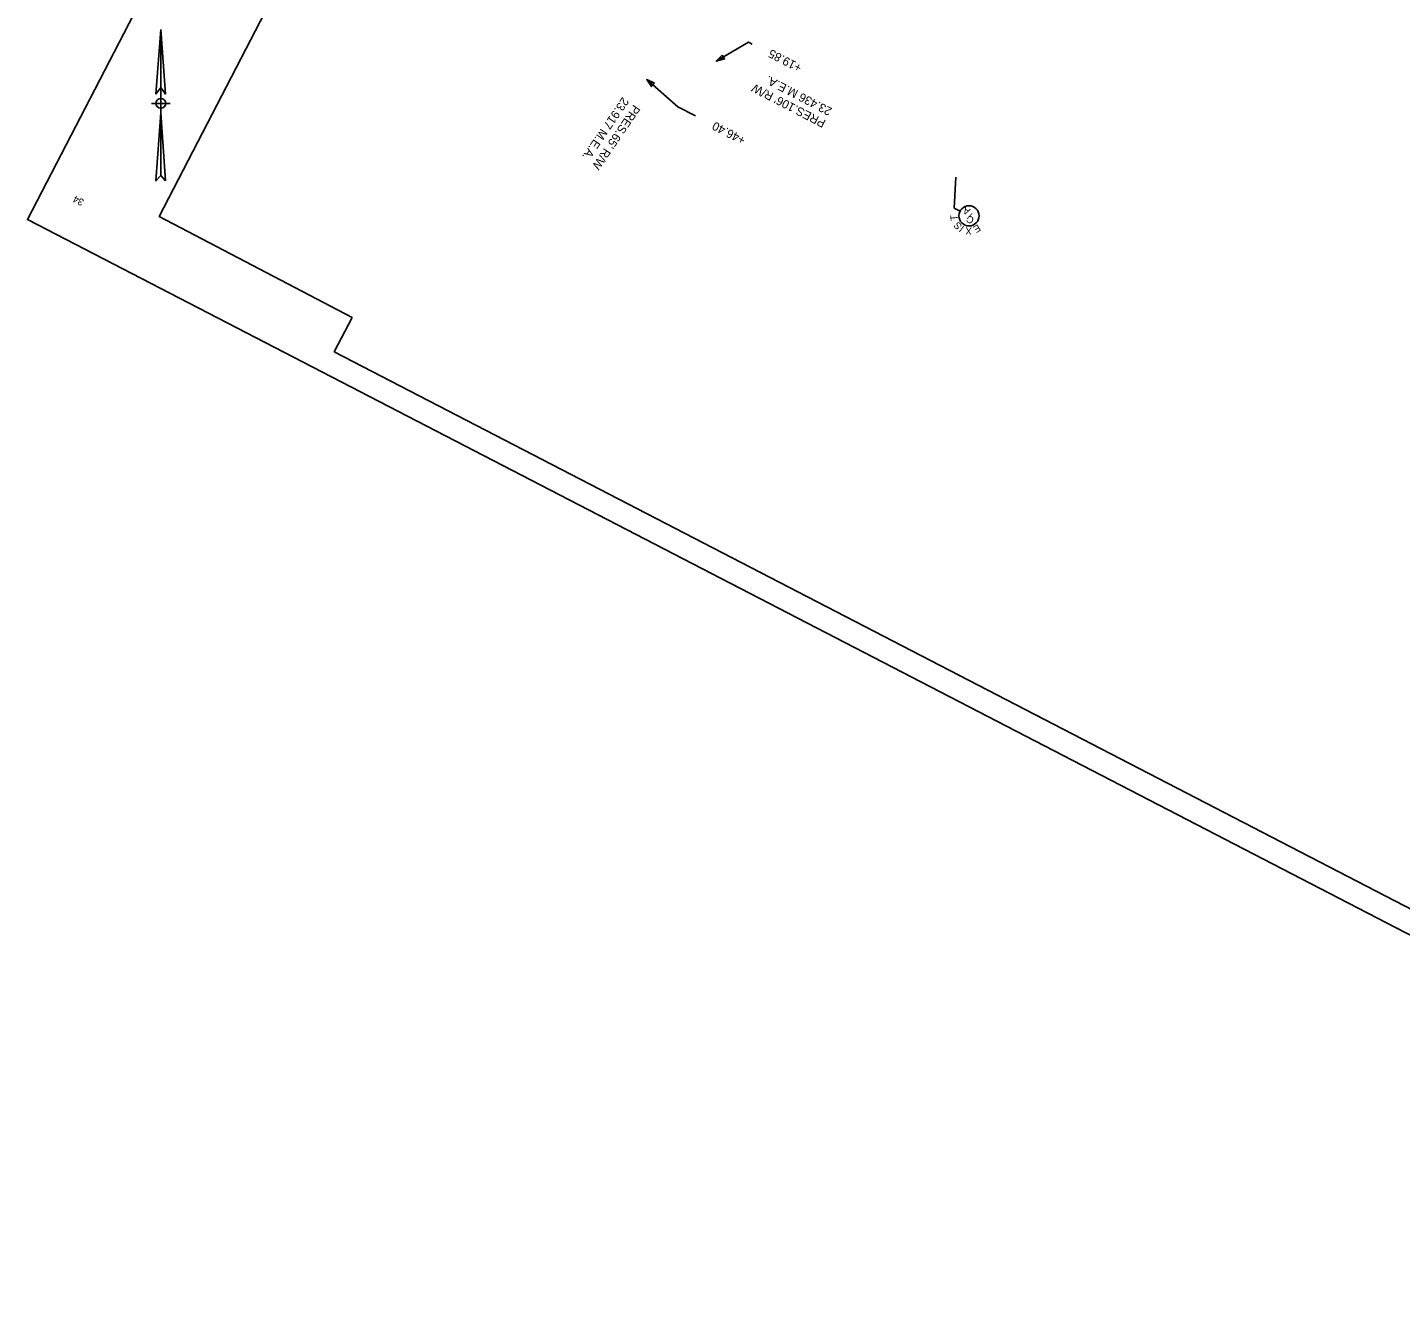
# Model space of a CAD drawing. Extents: x 1605035 to 1606962, y 1094993 to 1096933.
# Drawn here: x 1605035 to 1605999, y 1095130 to 1096034 of the extents above; entities that cross this region are included whole.
import ezdxf

# ---------------------------------------------------------------- set-up
doc = ezdxf.new("R2010")
doc.units = 0
for name, color, linetype in [('RD_EX_Bldg', 7, 'Continuous'), ('RD_EX_DV_Prop', 7, 'Continuous'), ('RD_EX_GuardRail', 7, 'Continuous'), ('RD_EX_H2O', 7, 'Continuous'), ('RD_EX_RW', 7, 'Continuous'), ('RD_HC_Data_Rel', 7, 'Continuous')]:
    doc.layers.add(name, color=color, linetype=linetype)

msp = doc.modelspace()

# ---------------------------------------------------------------- linework, layer by layer
at = {"layer": 'RD_EX_Bldg'}
msp.add_lwpolyline([(1606446.59, 1095187.39), (1605250.25, 1095806.81), (1605262.71, 1095830.87), (1605127.37, 1095901.84), (1605543.16, 1096704.91), (1606875.21, 1096015.23)], close=True, dxfattribs=at)
msp.add_lwpolyline([(1606446.59, 1095187.39), (1605250.25, 1095806.81), (1605262.71, 1095830.87), (1605127.37, 1095901.84), (1605543.16, 1096704.91), (1606875.21, 1096015.23)], close=True, dxfattribs=at)
at = {"layer": 'RD_EX_DV_Prop'}
for p, q in [((1605128.49, 1096033.09), (1605125.07, 1095987.78)), ((1605128.49, 1095992.43), (1605125.07, 1095987.78)), ((1605128.49, 1095992.43), (1605128.49, 1095974.59)), ((1605135.01, 1095981.2), (1605122.03, 1095981.2)), ((1605128.49, 1095974.59), (1605131.9, 1095926.75)), ((1605131.9, 1095926.75), (1605128.49, 1095930.57))]:
    msp.add_line(p, q, dxfattribs=at)
for points in [[(1605128.49, 1096033.09), (1605131.9, 1095987.78), (1605128.49, 1095992.43)], [(1605128.49, 1095974.59), (1605128.49, 1095930.57), (1605125.07, 1095926.75)]]:
    msp.add_lwpolyline(points, close=True, dxfattribs=at)
msp.add_circle((1605128.52, 1095981.2), 3.45, dxfattribs=at)
at = {"layer": 'RD_EX_GuardRail'}
msp.add_lwpolyline([(1606522.48, 1095129.57), (1605034.93, 1095899.57), (1605474.61, 1096748.97), (1606962.16, 1095978.97)], close=True, dxfattribs=at)
at = {"layer": 'RD_EX_RW'}
for points in [[(1605543.54, 1096022.85), (1605541.05, 1096024.14), (1605518.37, 1096010.76)], [(1605503.69, 1095972.35), (1605491.42, 1095978.71), (1605469.58, 1095997.93)]]:
    msp.add_lwpolyline(points, dxfattribs=at)
for points in [[(1605522.57, 1096015.04), (1605518.37, 1096010.76), (1605524.15, 1096012.36)], [(1605474.95, 1095995.27), (1605469.58, 1095997.93), (1605472.9, 1095992.94)]]:
    msp.add_lwpolyline(points, close=True, dxfattribs=at)
at = {"layer": 'RD_HC_Data_Rel'}
for p, q in [((1605685.35, 1095907.6), (1605686.57, 1095929.42)), ((1605689.42, 1095905.5), (1605685.35, 1095907.6))]:
    msp.add_line(p, q, dxfattribs=at)
msp.add_circle((1605695.71, 1095902.25), 7.08, dxfattribs=at)

# ---------------------------------------------------------------- texts
at = {"layer": 'RD_EX_H2O'}
msp.add_text('34', height=5, rotation=152.6325, dxfattribs=at).set_placement((1605075.09, 1095913.37))
at = {"layer": 'RD_EX_RW'}
for s, rotation, p in [('+19.85', 152.62682, (1605578.95, 1096008.03)), ('23.436 M.E.A.', 152.62682, (1605600.04, 1095977.57)), ("PRES.106' R/W", 152.62682, (1605595.68, 1095969.13)), ('23.917 M.E.A.', 235.77267, (1605452.55, 1095986)), ("PRES.65' R/W", 235.77267, (1605460.41, 1095980.65)), ('+46.40', 152.62682, (1605539.47, 1095957.21))]:
    msp.add_text(s, height=6, rotation=rotation, dxfattribs=at).set_placement(p)
at = {"layer": 'RD_HC_Data_Rel'}
for s, rotation, p in [('T', 95.68421, (1605687.9, 1095899.09)), ('A', 152.63087, (1605697.02, 1095906.8)), ('C', 152.63087, (1605699.76, 1095900.59)), ('/', 152.63087, (1605698.1, 1095903.82)), ('S', 130.84568, (1605691.14, 1095895.17)), ('I', 142.56618, (1605692.68, 1095894.39)), ('X', 177.72765, (1605697.75, 1095894.07)), ('E', 211.21477, (1605701.92, 1095896.56))]:
    msp.add_text(s, height=5, rotation=rotation, dxfattribs=at).set_placement(p)

doc.saveas('drawing.dxf')
